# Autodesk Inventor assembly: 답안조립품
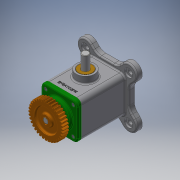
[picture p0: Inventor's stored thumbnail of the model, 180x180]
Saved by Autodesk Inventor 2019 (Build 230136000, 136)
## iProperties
Created: 2021-01
Part Number: 답안조립품
Material: 일반
Document SubType Name: Assembly
Designer: 3dpro23
Author: 3dpro23
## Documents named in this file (11)
- C:\Users\3dpro23\Desktop\710114V1005\답안조립품.iam
- C:\Users\3dpro23\Desktop\710114V1005\본체.ipt
- C:\Users\3dpro23\Desktop\710114V1005\베어링 6203.ipt
- C:\Users\3dpro23\Desktop\710114V1005\볼트 M4.ipt
- C:\Users\3dpro23\Desktop\710114V1005\부시.ipt
- C:\Users\3dpro23\Desktop\710114V1005\스퍼기어.ipt
- C:\Users\3dpro23\Desktop\710114V1005\슬라이더.ipt
- C:\Users\3dpro23\Desktop\710114V1005\오일 실.ipt
- C:\Users\3dpro23\Desktop\710114V1005\커버.ipt
- C:\Users\3dpro23\Desktop\710114V1005\키 4 x 4 x 14.ipt
- C:\Users\3dpro23\Desktop\710114V1005\편심축.ipt
